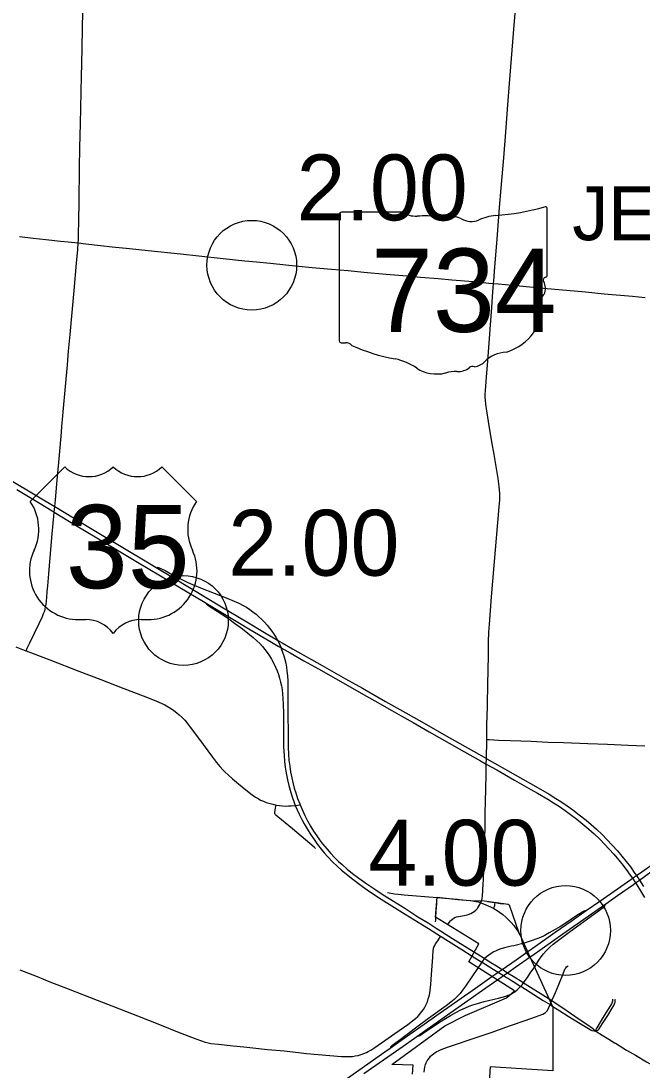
# Model space of a CAD drawing. Extents: x 1597222 to 1925846, y 496284 to 911751.
# Drawn here: x 1648365 to 1658757, y 590130 to 607664 of the extents above; entities that cross this region are included whole.
import ezdxf

# ---------------------------------------------------------------- set-up
doc = ezdxf.new("R2010")
doc.units = 0
for name, color, linetype in [('Default', 7, 'Continuous'), ('GM_X_City_Street', 7, 'Continuous'), ('GM_X_Corporation', 7, 'Continuous'), ('GM_X_County_Road', 7, 'Continuous'), ('GM_X_Interchange_Ramps', 7, 'Continuous'), ('GM_X_Interstate_Route', 7, 'Continuous'), ('GM_X_State_Route', 7, 'Continuous'), ('GM_X_State_Shield', 7, 'Continuous'), ('GM_X_Township_Road', 7, 'Continuous'), ('GM_X_Township_Text', 7, 'Continuous'), ('GM_X_US_Route', 7, 'Continuous'), ('GM_X_US_Shield', 7, 'Continuous')]:
    doc.layers.add(name, color=color, linetype=linetype)

msp = doc.modelspace()

# ---------------------------------------------------------------- linework, layer by layer
at = {"layer": 'Default'}
for centre in [(1652228, 603582), (1652228, 603582), (1651085, 597643), (1651085, 597643), (1657479, 592462), (1657479, 592462)]:
    msp.add_circle(centre, 750, dxfattribs=at)
at = {"layer": 'GM_X_City_Street'}
for points in [[(1655504, 592558), (1655531, 592598), (1655550, 592623), (1655561, 592634), (1655586, 592654), (1655612, 592671), (1655626, 592678), (1655640, 592684), (1655655, 592688), (1655686, 592696), (1655782, 592713), (1655830, 592723), (1655862, 592733), (1655893, 592747), (1655923, 592763), (1655951, 592782), (1655976, 592803), (1656002, 592830), (1656010, 592841), (1656027, 592869), (1656041, 592895), (1656056, 592926)], [(1656056, 592926), (1656104, 592909), (1656146, 592892), (1656220, 592858), (1656275, 592830)], [(1656170, 592944), (1656250, 592936), (1656298, 592929)], [(1656275, 592830), (1656280, 592843), (1656287, 592862), (1656292, 592881), (1656294, 592899), (1656298, 592929)], [(1656298, 592929), (1656383, 592916), (1656433, 592910)], [(1656275, 592830), (1656278, 592828), (1656334, 592794), (1656375, 592767), (1656427, 592728), (1656477, 592686), (1656524, 592641), (1656569, 592593), (1656611, 592543), (1656650, 592491), (1656678, 592450), (1656698, 592418)], [(1655109, 590095), (1655116, 590143), (1655123, 590175), (1655136, 590222), (1655147, 590252), (1655162, 590281), (1655180, 590308), (1655199, 590334), (1655220, 590359), (1655243, 590382), (1655267, 590403), (1655294, 590421), (1655321, 590438), (1655350, 590452), (1655395, 590472), (1655503, 590510), (1656030, 590690), (1656231, 590759), (1656556, 590872), (1656804, 590958), (1656974, 591018), (1657096, 591065), (1657126, 591080), (1657140, 591089), (1657153, 591100), (1657165, 591112), (1657175, 591125), (1657218, 591223)]]:
    msp.add_lwpolyline(points, dxfattribs=at)
at = {"layer": 'GM_X_Corporation'}
msp.add_lwpolyline([(1654918, 590062), (1654930, 590211), (1654570, 590221), (1655458, 590869), (1655796, 591042), (1656487, 591335), (1656623, 591453), (1655861, 591941), (1656029, 592237), (1655300, 592684), (1655329, 593018), (1655677, 592981), (1655883, 592965), (1655960, 592960), (1656085, 592963), (1656519, 592902), (1656534, 592889), (1656697, 592423), (1656742, 592333), (1656882, 592022), (1657263, 591181), (1657264, 590116), (1656216, 590184), (1656071, 587942)], dxfattribs=at)
at = {"layer": 'GM_X_County_Road'}
for points in [[(1649322, 603954), (1649326, 604008), (1649329, 604106), (1649333, 604319), (1649337, 604648), (1649344, 605205), (1649350, 605550), (1649359, 605943), (1649377, 606747), (1649382, 606944), (1649394, 607518), (1649403, 607846), (1649412, 608206), (1649417, 608436), (1649417, 608447)], [(1656273, 603277), (1656277, 603319), (1656295, 603548), (1656333, 604022), (1656355, 604317), (1656373, 604545), (1656400, 604872), (1656442, 605379), (1656476, 605804), (1656512, 606261), (1656541, 606621), (1656564, 606899), (1656586, 607177), (1656608, 607454), (1656641, 607863)], [(1649061, 600997), (1649072, 601132), (1649111, 601557), (1649142, 601917), (1649162, 602146), (1649187, 602423), (1649232, 602913), (1649254, 603158), (1649294, 603616), (1649315, 603845), (1649322, 603954)], [(1656171, 596177), (1656173, 596236), (1656179, 596581), (1656182, 596810), (1656186, 597072), (1656190, 597286), (1656195, 597449), (1656203, 597580), (1656239, 598038), (1656284, 598561), (1656307, 598822), (1656346, 599279), (1656369, 599541), (1656377, 599655), (1656379, 599721), (1656378, 599770), (1656375, 599820), (1656368, 599885), (1656349, 600015), (1656281, 600419), (1656246, 600630), (1656188, 600969), (1656159, 601147), (1656143, 601260), (1656137, 601325), (1656134, 601374), (1656134, 601423), (1656137, 601489), (1656160, 601783), (1656175, 601979), (1656221, 602584), (1656243, 602878), (1656257, 603058), (1656273, 603277)], [(1648806, 598126), (1648815, 598225), (1648831, 598421), (1648860, 598764), (1648890, 599090), (1648916, 599385), (1648922, 599455), (1648930, 599547), (1648941, 599662), (1648971, 599989), (1648997, 600283), (1649037, 600724), (1649057, 600953), (1649061, 600997)], [(1648451, 597137), (1648471, 597180), (1648513, 597269), (1648669, 597594), (1648726, 597713), (1648745, 597758), (1648762, 597803), (1648771, 597834), (1648778, 597866), (1648786, 597914), (1648797, 598029), (1648806, 598126)], [(1648280, 597204), (1648448, 597138), (1648451, 597137)], [(1648451, 597137), (1648570, 597091), (1648846, 596986), (1649336, 596797), (1649704, 596655), (1650087, 596508), (1650408, 596383), (1650622, 596300), (1650713, 596262), (1650772, 596234), (1650829, 596202), (1650884, 596168), (1650924, 596140), (1650976, 596100), (1651013, 596067), (1651060, 596022), (1651105, 595975), (1651148, 595925), (1651198, 595861), (1651336, 595677), (1651569, 595360), (1651639, 595268), (1651692, 595205), (1651747, 595144), (1651782, 595109), (1651831, 595065), (1651905, 594999), (1652006, 594915), (1652069, 594864), (1652183, 594769), (1652235, 594729), (1652273, 594703)], [(1656159, 595654), (1656163, 595876), (1656168, 596072), (1656171, 596177)], [(1656134, 594357), (1656134, 594417), (1656142, 594827), (1656148, 595073), (1656151, 595243), (1656153, 595335), (1656153, 595351), (1656158, 595614), (1656159, 595654)], [(1656159, 595654), (1656202, 595652), (1656358, 595645), (1656557, 595636), (1656901, 595624), (1657179, 595612), (1657442, 595603), (1657851, 595587), (1658179, 595574), (1658523, 595560), (1658802, 595549)], [(1652273, 594703), (1652289, 594691), (1652332, 594666), (1652376, 594643), (1652421, 594622), (1652467, 594604), (1652514, 594589), (1652577, 594571), (1652633, 594559)], [(1652633, 594559), (1652642, 594557), (1652690, 594549), (1652740, 594544), (1652789, 594542), (1652839, 594543), (1652888, 594547), (1652956, 594552)], [(1652956, 594552), (1653037, 594560)], [(1656102, 593298), (1656107, 593368), (1656113, 593499), (1656120, 593729), (1656132, 594220), (1656134, 594357)], [(1656056, 592926), (1656064, 592942), (1656069, 592954), (1656074, 592968), (1656077, 592978), (1656080, 592993), (1656083, 593010), (1656086, 593029), (1656087, 593041), (1656093, 593123), (1656100, 593254), (1656102, 593298)], [(1654499, 593099), (1654613, 593077), (1654678, 593067), (1654777, 593057), (1655329, 593012)], [(1655308, 592682), (1655315, 592781), (1655321, 592914), (1655325, 592964), (1655329, 593012)], [(1655329, 593012), (1655458, 593002), (1655668, 592983), (1655702, 592981)], [(1655702, 592981), (1655814, 592971), (1655885, 592962)], [(1655885, 592962), (1655894, 592961), (1655975, 592948), (1656017, 592939), (1656032, 592934), (1656046, 592929), (1656056, 592926)], [(1655302, 592605), (1655305, 592640), (1655308, 592682)], [(1656698, 592418), (1656730, 592361), (1656737, 592346)], [(1657248, 591290), (1657286, 591373), (1657309, 591424), (1657363, 591558), (1657435, 591740), (1657459, 591800), (1657466, 591814), (1657475, 591827), (1657484, 591840), (1657495, 591852), (1657519, 591874)], [(1657218, 591223), (1657237, 591265), (1657248, 591290)], [(1657983, 590777), (1657998, 590822), (1658001, 590828), (1658003, 590833), (1658006, 590837), (1658062, 590929), (1658131, 591041), (1658236, 591208), (1658253, 591237), (1658260, 591252), (1658265, 591268), (1658267, 591285), (1658268, 591302), (1658270, 591317)], [(1657983, 590777), (1658026, 590802), (1658031, 590806), (1658036, 590812), (1658039, 590817), (1658096, 590905), (1658140, 590974), (1658183, 591042), (1658260, 591166), (1658285, 591208), (1658299, 591236), (1658304, 591251), (1658307, 591266), (1658310, 591298), (1658311, 591314)]]:
    msp.add_lwpolyline(points, dxfattribs=at)
at = {"layer": 'GM_X_Interchange_Ramps'}
for points in [[(1656727, 591530), (1656750, 591555), (1656773, 591588), (1656788, 591608), (1656818, 591650), (1656838, 591679), (1656885, 591749), (1656962, 591856), (1657032, 591966), (1657070, 592020), (1657110, 592072), (1657152, 592122), (1657186, 592157), (1657222, 592191), (1657271, 592234), (1657336, 592284), (1657560, 592449), (1657944, 592727), (1658109, 592847), (1658121, 592859), (1658132, 592873), (1658139, 592884), (1658152, 592909)], [(1657825, 592796), (1657810, 592793), (1657798, 592790), (1657785, 592786), (1657774, 592781), (1657764, 592775), (1657652, 592703), (1657502, 592601), (1657391, 592529), (1657306, 592477), (1657205, 592421), (1657117, 592375), (1657057, 592347), (1656996, 592321), (1656903, 592288), (1656783, 592249), (1656614, 592208), (1656566, 592198), (1656456, 592171), (1656394, 592153), (1656348, 592138), (1656304, 592119), (1656275, 592104), (1656234, 592079), (1656195, 592051), (1656157, 592021), (1656124, 591993), (1656119, 591987), (1656101, 591967), (1656079, 591935)], [(1656079, 591935), (1656055, 591899), (1656017, 591843), (1655803, 591529), (1655755, 591462), (1655714, 591411), (1655681, 591375), (1655647, 591340), (1655611, 591306), (1655560, 591264), (1655482, 591205), (1655185, 590989), (1654990, 590845), (1654687, 590619), (1654568, 590534), (1654557, 590524), (1654551, 590515), (1654543, 590497)], [(1654987, 590691), (1655010, 590697), (1655026, 590701), (1655039, 590707), (1655117, 590760), (1655195, 590813), (1655371, 590928), (1655468, 590991), (1655553, 591042), (1655639, 591090), (1655727, 591136), (1655801, 591171), (1655862, 591196), (1655924, 591219), (1656002, 591243), (1656114, 591273), (1656353, 591332), (1656480, 591367), (1656518, 591379), (1656558, 591395), (1656605, 591423), (1656636, 591444), (1656668, 591470), (1656690, 591490), (1656704, 591506), (1656727, 591530)]]:
    msp.add_lwpolyline(points, dxfattribs=at)
at = {"layer": 'GM_X_Interstate_Route'}
for points in [[(1653830, 589995), (1654453, 590434), (1654543, 590497), (1654681, 590595), (1654870, 590727), (1655109, 590894), (1655324, 591045), (1655971, 591498), (1656246, 591691), (1656313, 591737), (1656351, 591764), (1656417, 591811), (1656651, 591974), (1656845, 592111), (1656976, 592202), (1657306, 592435), (1657572, 592620), (1657825, 592796), (1658052, 592954), (1658347, 593161), (1658572, 593317), (1658597, 593334), (1658664, 593382), (1658753, 593445), (1658927, 593564)], [(1656885, 592022), (1656911, 592040), (1657433, 592405), (1657728, 592612), (1658152, 592909), (1658346, 593045), (1658615, 593233), (1658648, 593257), (1658716, 593305), (1658907, 593440)], [(1656376, 591665), (1656439, 591709), (1656506, 591756), (1656648, 591856), (1656885, 592022)], [(1654103, 590073), (1654759, 590531), (1654987, 590691), (1655259, 590882), (1655544, 591082), (1656032, 591424), (1656328, 591631), (1656333, 591634)], [(1656333, 591634), (1656376, 591665)]]:
    msp.add_lwpolyline(points, dxfattribs=at)
at = {"layer": 'GM_X_State_Route'}
for points in [[(1648341, 604060), (1648569, 604036), (1648781, 604013), (1649026, 603985), (1649157, 603972), (1649322, 603954), (1649450, 603939), (1649695, 603912), (1649890, 603892), (1650184, 603861), (1650494, 603827), (1651033, 603771), (1651343, 603739), (1651751, 603694), (1652110, 603658), (1652306, 603638), (1652534, 603614), (1652697, 603598), (1652845, 603583)], [(1652845, 603583), (1652959, 603572), (1653236, 603544), (1653563, 603514), (1653841, 603491), (1654102, 603467), (1654475, 603435)], [(1654475, 603435), (1654478, 603435), (1654822, 603404), (1655050, 603384), (1655344, 603359), (1655573, 603340), (1655933, 603308), (1656194, 603284), (1656273, 603277), (1656358, 603269), (1656587, 603249), (1657109, 603200), (1657812, 603135), (1658122, 603105), (1658596, 603062), (1658809, 603043)], [(1650626, 598530), (1650639, 598533), (1650649, 598532), (1650664, 598528), (1650777, 598478), (1650953, 598381), (1651070, 598321), (1651158, 598278), (1651263, 598232), (1651370, 598188), (1651600, 598101), (1651829, 598012), (1651935, 597968), (1652009, 597934), (1652082, 597897), (1652138, 597864), (1652193, 597828), (1652246, 597790), (1652298, 597750), (1652347, 597707), (1652395, 597663), (1652441, 597616), (1652485, 597568), (1652526, 597517), (1652565, 597465), (1652601, 597411), (1652635, 597355), (1652656, 597317), (1652667, 597297), (1652695, 597239), (1652717, 597188), (1652721, 597178), (1652744, 597117), (1652763, 597055), (1652781, 596992), (1652795, 596928), (1652806, 596864), (1652815, 596799), (1652823, 596718), (1652828, 596636), (1652830, 596521), (1652831, 596177), (1652834, 595653), (1652837, 595521), (1652842, 595407), (1652850, 595308), (1652862, 595210), (1652877, 595113), (1652895, 595016), (1652914, 594936), (1652939, 594841), (1652962, 594762), (1652994, 594669), (1653030, 594577), (1653037, 594560), (1653068, 594486), (1653117, 594382), (1653161, 594294), (1653209, 594208), (1653261, 594124), (1653315, 594042), (1653363, 593975), (1653412, 593910), (1653486, 593821), (1653551, 593747), (1653619, 593676), (1653677, 593618), (1653738, 593563), (1653826, 593488), (1653915, 593416), (1654020, 593337), (1654153, 593241), (1654302, 593139), (1654411, 593067), (1654787, 592833), (1655008, 592692), (1655176, 592589), (1655315, 592502), (1655427, 592431), (1655436, 592425), (1655675, 592274), (1655955, 592099), (1656081, 592021), (1656124, 591993), (1656130, 591989), (1656226, 591929), (1656323, 591869), (1656417, 591811), (1656448, 591791), (1656506, 591756), (1656601, 591697), (1656761, 591596), (1656773, 591588), (1656800, 591572), (1657141, 591358), (1657248, 591290), (1657271, 591275), (1657434, 591169), (1657559, 591082), (1657721, 590970), (1657831, 590897), (1657928, 590831), (1657934, 590827), (1657941, 590820), (1657983, 590777)], [(1651466, 597931), (1651466, 597927), (1651471, 597919), (1651479, 597910), (1651490, 597901), (1651819, 597686), (1651940, 597601), (1652072, 597504), (1652163, 597434), (1652252, 597361), (1652313, 597306), (1652360, 597259), (1652404, 597210), (1652446, 597159), (1652485, 597106), (1652522, 597052), (1652556, 596996), (1652588, 596938), (1652624, 596864), (1652650, 596803), (1652673, 596741), (1652692, 596678), (1652709, 596615), (1652723, 596550), (1652734, 596486), (1652743, 596420), (1652749, 596338), (1652754, 596240), (1652757, 596092), (1652757, 595810)], [(1652757, 595810), (1652757, 595649), (1652760, 595534), (1652768, 595387), (1652776, 595289), (1652787, 595191), (1652803, 595094), (1652825, 594981), (1652847, 594886), (1652869, 594807), (1652898, 594713), (1652943, 594585), (1652956, 594552)], [(1652956, 594552), (1652986, 594479), (1653021, 594405), (1653064, 594317), (1653102, 594244), (1653152, 594160), (1653214, 594063), (1653269, 593981), (1653326, 593902), (1653387, 593824), (1653439, 593761), (1653494, 593700), (1653585, 593606), (1653656, 593537), (1653729, 593472), (1653779, 593430)], [(1653779, 593430), (1653804, 593409), (1653895, 593338), (1654079, 593200), (1654158, 593143)], [(1654158, 593143), (1654159, 593143), (1654349, 593015), (1654794, 592736), (1655086, 592554)], [(1655086, 592554), (1655185, 592493), (1655386, 592366), (1655395, 592361), (1655477, 592309), (1655743, 592146), (1655917, 592035)], [(1655917, 592035), (1656079, 591935), (1656085, 591931), (1656206, 591855), (1656268, 591816), (1656321, 591783), (1656351, 591764), (1656410, 591728)], [(1656410, 591728), (1656439, 591709), (1656487, 591679), (1656538, 591647), (1656571, 591627), (1656603, 591607), (1656714, 591538), (1656727, 591530), (1657105, 591293), (1657218, 591223)], [(1657218, 591223), (1657262, 591194), (1657381, 591117), (1657522, 591030), (1657720, 590910), (1657890, 590808), (1657907, 590797), (1657915, 590793), (1657923, 590790), (1657983, 590777)], [(1657983, 590777), (1658091, 590710), (1658202, 590645), (1658299, 590586)], [(1658299, 590586), (1658313, 590577), (1658500, 590462), (1658646, 590376), (1658832, 590268), (1658970, 590188)]]:
    msp.add_lwpolyline(points, dxfattribs=at)
at = {"layer": 'GM_X_State_Shield'}
for p, q in [((1653692, 604433), (1653692, 602319)), ((1654745, 604469), (1653726, 604469)), ((1657172, 603416), (1657172, 604521)), ((1657172, 603416), (1657172, 603416))]:
    msp.add_line(p, q, dxfattribs=at)
for centre, major_axis, start_param, end_param in [((1653732, 604437), (40.3, 0), 1.712693, 3.28349), ((1654988, 604714), (391, 0), 4.042523, 4.731795), ((1655932, 607350), (3691, 0), 4.814394, 5.042369), ((1657134, 604526), (38.7, 0), 6.141152, 7.989035), ((1655118, 603283), (1404, 0), 1.404758, 1.657858), ((1655436, 604448), (113, 0), 3.836095, 5.185415), ((1655602, 604204), (235, 0), 0.950623, 2.079405), ((1655905, 604539), (282, 0), 4.081561, 5.145723), ((1656403, 603824), (743, 0), 1.699011, 2.107814), ((1657163, 603335), (60, 0), 1.883978, 3.671073), ((1657131, 603412), (41.5, 0), 5.05454, 6.418171), ((1656782, 603195), (360, 0), 5.934695, 6.695948), ((1657311, 602953), (262, 0), 2.387724, 3.262537), ((1656139, 602813), (923, 0), 5.101752, 6.440018), ((1653732, 602315), (40.7, 0), 3.00124, 4.508301), ((1653738, 602531), (310, 0), 4.665946, 4.897461), ((1653802, 602197), (112, 0), 0.519207, 1.627899), ((1655215, 604096), (2665, 0), 4.195997, 4.488961), ((1654420, 601370), (834, 0), 0.823519, 1.323587), ((1655888, 602115), (298, 0), 4.937069, 5.64225), ((1656528, 601726), (506, 0), 1.647645, 2.488434), ((1655322, 602187), (529, 0), 4.026481, 4.996735), ((1655628, 601456), (435, 0), 1.495662, 1.94098), ((1655667, 602029), (282, 0), 4.691044, 5.507374), ((1655922, 601824), (79.4, 0), 1.147584, 2.315152)]:
    msp.add_ellipse(centre, major_axis=major_axis, ratio=0.8, start_param=start_param, end_param=end_param, dxfattribs=at)
at = {"layer": 'GM_X_Township_Road'}
for points in [[(1653296, 593831), (1653271, 593853), (1652906, 594161), (1652665, 594361), (1652628, 594392), (1652623, 594398), (1652618, 594404), (1652615, 594411), (1652613, 594418), (1652613, 594425), (1652613, 594433), (1652626, 594513), (1652633, 594559)], [(1655257, 592051), (1655260, 592106), (1655263, 592137), (1655266, 592152), (1655270, 592167), (1655275, 592182), (1655288, 592210), (1655304, 592238), (1655339, 592292), (1655383, 592361), (1655386, 592366)], [(1653746, 590357), (1653812, 590354), (1653861, 590354), (1653910, 590358), (1653959, 590365), (1654007, 590375), (1654055, 590388), (1654101, 590404), (1654147, 590423), (1654176, 590437), (1654219, 590461), (1654287, 590507), (1654623, 590743), (1654838, 590893), (1654917, 590951), (1654969, 590993), (1655005, 591026), (1655038, 591062), (1655069, 591100), (1655098, 591140), (1655123, 591182), (1655145, 591226), (1655165, 591271), (1655181, 591318), (1655194, 591365), (1655205, 591413), (1655212, 591462), (1655222, 591560), (1655232, 591724), (1655255, 592018), (1655257, 592051)], [(1648344, 591805), (1648634, 591692), (1648848, 591606), (1649153, 591487), (1649642, 591296), (1649887, 591201), (1650116, 591112), (1650315, 591035), (1650498, 590963), (1650712, 590879), (1650987, 590771), (1651292, 590651), (1651385, 590616), (1651447, 590596), (1651495, 590584), (1651543, 590576), (1651673, 590561), (1651918, 590535), (1652097, 590516), (1652244, 590499), (1652489, 590473), (1652636, 590461), (1652767, 590449), (1653011, 590421), (1653142, 590406), (1653338, 590389), (1653534, 590373), (1653730, 590358), (1653746, 590357)]]:
    msp.add_lwpolyline(points, dxfattribs=at)
at = {"layer": 'GM_X_US_Route'}
for points in [[(1648036, 600083), (1648768, 599644), (1648930, 599547), (1649527, 599189), (1650526, 598589), (1650626, 598530), (1650920, 598354), (1651483, 598017), (1651722, 597873), (1652143, 597619), (1652440, 597444), (1652656, 597317), (1652737, 597270), (1652908, 597172), (1653407, 596889), (1653793, 596671), (1654079, 596510), (1654464, 596292), (1654807, 596099), (1655149, 595904), (1655478, 595718), (1655935, 595460), (1656153, 595335), (1656162, 595329), (1656633, 595063), (1657019, 594844), (1657204, 594739), (1657316, 594671), (1657399, 594618), (1657507, 594544), (1657600, 594477), (1657705, 594398), (1657820, 594306), (1657907, 594232), (1657993, 594156), (1658088, 594065), (1658169, 593984), (1658259, 593889), (1658347, 593792), (1658421, 593705), (1658493, 593615), (1658562, 593524), (1658639, 593417), (1658664, 593382), (1658716, 593305), (1658784, 593199)], [(1648294, 599833), (1648688, 599597), (1648885, 599478), (1648922, 599455), (1649276, 599239), (1649784, 598937), (1650290, 598633), (1650904, 598267)], [(1650904, 598267), (1651023, 598196), (1651417, 597960), (1651466, 597931)], [(1651466, 597931), (1652050, 597581), (1652149, 597522), (1652557, 597279), (1652671, 597214), (1652717, 597188), (1652872, 597102), (1653100, 596972), (1653342, 596833), (1653627, 596672), (1653913, 596511)], [(1653913, 596511), (1654056, 596430), (1654284, 596300), (1654569, 596138), (1654726, 596050), (1654926, 595937), (1655198, 595783), (1655697, 595499), (1656054, 595297), (1656151, 595243), (1656326, 595146), (1656625, 594974), (1656895, 594820), (1657009, 594755), (1657180, 594656), (1657278, 594596), (1657375, 594534), (1657469, 594469), (1657562, 594402), (1657667, 594322), (1657769, 594239), (1657869, 594154), (1657954, 594077), (1658049, 593986), (1658130, 593905), (1658209, 593821), (1658286, 593736), (1658371, 593635), (1658442, 593546), (1658521, 593441), (1658544, 593409)], [(1658544, 593409), (1658597, 593334), (1658648, 593257), (1658671, 593225), (1658732, 593127), (1658799, 593014)]]:
    msp.add_lwpolyline(points, dxfattribs=at)
at = {"layer": 'GM_X_US_Shield'}
for p, q in [((1649097, 600214), (1648517, 599634)), ((1651302, 599634), (1650722, 600214)), ((1649329, 597661), (1649445, 597661)), ((1650374, 597661), (1650490, 597661))]:
    msp.add_line(p, q, dxfattribs=at)
for centre, radius, start, end in [((1649503, 600628), 580, 225.573, 314.427), ((1650316, 600628), 580, 225.573, 314.427), ((1647852, 599168), 812, 334.5471, 35.0009), ((1651967, 599168), 812, 144.9991, 205.4529), ((1649320, 598473), 812, 154.8319, 270.6383), ((1650499, 598473), 812, 269.3617, 25.1681), ((1649445, 597081), 580, 36.8699, 90), ((1650374, 597081), 580, 90, 143.1301)]:
    msp.add_arc(centre, radius, start, end, dxfattribs=at)

# ---------------------------------------------------------------- texts
at = {"layer": 'Default'}
for s, p in [('2.00', (1652978, 604332)), ('2.00', (1652978, 604332)), ('2.00', (1651835, 598393)), ('2.00', (1651835, 598393)), ('4.00', (1654178, 593212))]:
    msp.add_text(s, height=1100, dxfattribs=at).set_placement(p)
at = {"layer": 'GM_X_State_Shield'}
msp.add_text('734', height=1392.2, dxfattribs=at).set_placement((1654223, 602468))
at = {"layer": 'GM_X_Township_Text'}
msp.add_text('JEFFERSON', height=900, rotation=0, dxfattribs=at).set_placement((1657590, 604000))
at = {"layer": 'GM_X_US_Shield'}
msp.add_text('35', height=1392.2, dxfattribs=at).set_placement((1649117, 598183))

doc.saveas('drawing.dxf')
